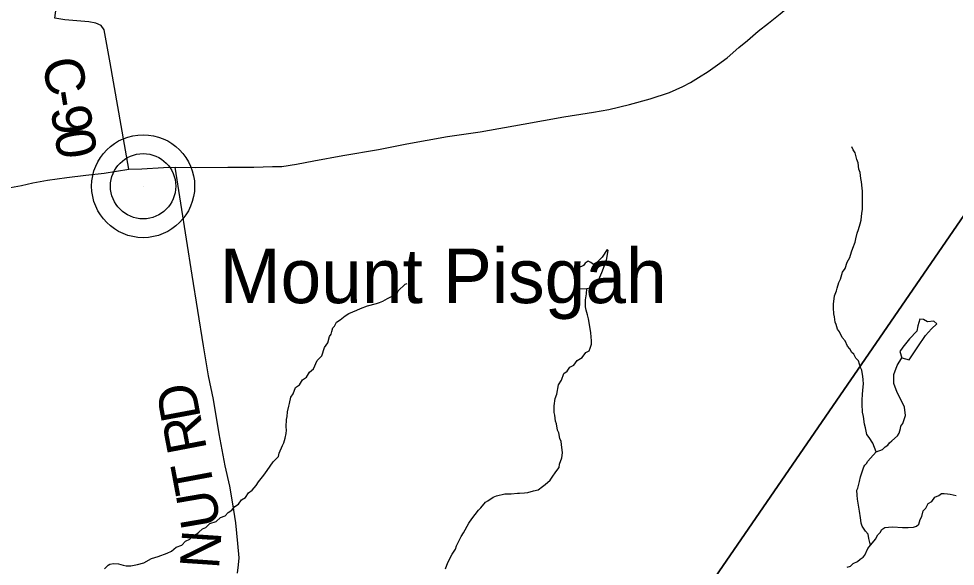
# Model space of a CAD drawing. Extents: x 0 to 39.3, y -3.9 to 22.
# Drawn here: x 3.453 to 4.806, y 14.774 to 15.566 of the extents above; entities that cross this region are included whole.
import ezdxf

# ---------------------------------------------------------------- set-up
doc = ezdxf.new("R2010")
doc.units = 0
for name, color, linetype in [('GM_X_Corporation', 7, 'Continuous'), ('GM_X_County_Road', 7, 'Continuous'), ('GM_X_County_Road_Text', 7, 'Continuous'), ('GM_X_Minor_Lake', 7, 'Continuous'), ('GM_X_Minor_River', 7, 'Continuous'), ('GM_X_State_Route', 7, 'Continuous'), ('GM_X_Township_Road', 7, 'Continuous'), ('GM_X_Township_Road_Text', 7, 'Continuous'), ('GM_X_Unincorporated', 7, 'Continuous'), ('GM_X_Unincorporated_Location', 7, 'Continuous'), ('GM_X_Unincorporated_Text', 7, 'Continuous')]:
    doc.layers.add(name, color=color, linetype=linetype)

msp = doc.modelspace()

# ---------------------------------------------------------------- linework, layer by layer
at = {"layer": 'GM_X_Corporation'}
for points in [[(6.2667, 17.3782), (6.0256, 17.0319), (5.8398, 16.7652), (5.744, 16.6289), (5.7424, 16.6266), (5.2028, 15.8376), (5.0728, 15.652), (4.2376, 14.4362), (4.2334, 14.4302), (3.9536, 14.0228), (3.9474, 14.0138), (3.8692, 13.9), (7.894, 13.9)], [(1.9, 13.9), (3.8692, 13.9), (3.9474, 14.0138), (3.9536, 14.0228), (4.2334, 14.4302), (4.2376, 14.4362), (5.0728, 15.652)]]:
    msp.add_lwpolyline(points, dxfattribs=at)
at = {"layer": 'GM_X_County_Road'}
msp.add_lwpolyline([(3.6118, 15.3483), (3.5847, 15.5024), (3.5762, 15.5497), (3.5717, 15.5564), (3.5644, 15.5596), (3.5541, 15.5613), (3.5196, 15.5645), (3.5047, 15.5667), (3.517, 15.6576), (3.5226, 15.7048), (3.5336, 15.7776), (3.5401, 15.8304), (3.5407, 15.8407), (3.5424, 15.8487), (3.5435, 15.8578), (3.543, 15.8618)], dxfattribs=at)
at = {"layer": 'GM_X_Minor_Lake'}
for points in [[(4.2735, 15.176), (4.2866, 15.1786), (4.2953, 15.199), (4.302, 15.2171), (4.3045, 15.2307), (4.303, 15.2323), (4.2956, 15.2214), (4.2883, 15.2135), (4.2833, 15.2106), (4.2796, 15.2137), (4.2754, 15.2156), (4.2712, 15.2123), (4.2689, 15.2093), (4.2616, 15.2056), (4.2569, 15.2)], [(4.2569, 15.2), (4.2561, 15.1928), (4.2581, 15.1814), (4.2614, 15.1752), (4.2735, 15.176)], [(4.7289, 15.0758), (4.7395, 15.0729), (4.752, 15.0917), (4.7629, 15.1079), (4.7714, 15.1176), (4.7795, 15.1247), (4.775, 15.1289), (4.7659, 15.1276), (4.7602, 15.1311), (4.7549, 15.1316), (4.7521, 15.1217), (4.7505, 15.1142)], [(4.7505, 15.1142), (4.7397, 15.1033), (4.7303, 15.0913), (4.726, 15.0846), (4.7289, 15.0758)]]:
    msp.add_lwpolyline(points, dxfattribs=at)
at = {"layer": 'GM_X_Minor_River'}
for points in [[(4.6918, 14.9395), (4.687, 14.9524), (4.6815, 14.9604), (4.6781, 14.9647), (4.6764, 14.9746), (4.6746, 14.9796), (4.6736, 14.991), (4.6718, 14.9972), (4.6713, 15.0086), (4.6714, 15.0139), (4.672, 15.0238), (4.6724, 15.028), (4.6729, 15.0341), (4.6733, 15.0375), (4.6731, 15.0443), (4.6724, 15.0485), (4.671, 15.0577), (4.6688, 15.0619), (4.6663, 15.0711), (4.6622, 15.075), (4.6593, 15.0811), (4.6563, 15.0834), (4.6537, 15.0888), (4.6504, 15.0923), (4.6471, 15.1003), (4.6426, 15.105), (4.6389, 15.113), (4.6356, 15.1169), (4.6338, 15.1238), (4.6323, 15.1272), (4.6313, 15.1349), (4.6303, 15.1395), (4.63, 15.1478), (4.6301, 15.1535), (4.631, 15.1611), (4.6315, 15.1653), (4.6343, 15.1725), (4.6355, 15.1763), (4.6379, 15.1846), (4.6403, 15.1892), (4.6428, 15.1994), (4.6471, 15.2046), (4.6499, 15.2141), (4.6534, 15.2205), (4.6562, 15.2289), (4.6579, 15.2342), (4.6611, 15.2429), (4.6623, 15.2478), (4.6644, 15.2561), (4.666, 15.261), (4.6684, 15.2694), (4.67, 15.2747), (4.671, 15.2846), (4.6718, 15.2902), (4.6721, 15.307), (4.6719, 15.3165), (4.6716, 15.3211), (4.6706, 15.3302), (4.6696, 15.3348), (4.6686, 15.3436), (4.6668, 15.3486), (4.6658, 15.3577), (4.6636, 15.3623), (4.6615, 15.3719), (4.6582, 15.3765), (4.6563, 15.3807)], [(3.8283, 14.9332), (3.8291, 14.9378), (3.8339, 14.9491), (3.8359, 14.9525), (3.8379, 14.9597), (3.8392, 14.9661), (3.8396, 14.9711), (3.8393, 14.976), (3.8399, 14.9863), (3.8404, 14.9909), (3.8413, 14.9977), (3.8429, 15.0057), (3.8441, 15.0098), (3.8458, 15.0189), (3.8493, 15.0238), (3.8529, 15.0325), (3.8583, 15.0366), (3.8626, 15.0438), (3.8684, 15.0475), (3.8727, 15.055), (3.8785, 15.0599), (3.8841, 15.0719), (3.8907, 15.0783), (3.8947, 15.0908), (3.8994, 15.0972), (3.9019, 15.1067), (3.9042, 15.1097), (3.905, 15.1138), (3.9066, 15.1188), (3.909, 15.1214), (3.9117, 15.127), (3.9171, 15.1308), (3.9245, 15.1363), (3.9299, 15.1397), (3.9414, 15.1444), (3.9467, 15.147), (3.9567, 15.1506), (3.9697, 15.1542), (3.9739, 15.1557), (3.9789, 15.1575), (3.9824, 15.1597), (3.9854, 15.1612), (3.9924, 15.1649), (3.9997, 15.1689), (4.0012, 15.1723), (4.0109, 15.1821), (4.014, 15.1831)], [(4.2804, 15.0956), (4.2805, 15.1002), (4.2796, 15.112), (4.2778, 15.1211), (4.2761, 15.1322), (4.2747, 15.1379), (4.2725, 15.1445), (4.2719, 15.1494), (4.2719, 15.1525), (4.2716, 15.1567), (4.2717, 15.1597), (4.273, 15.168), (4.2735, 15.176)], [(4.0694, 14.7707), (4.0726, 14.7798), (4.0789, 14.7915), (4.084, 14.799), (4.0852, 14.8039), (4.0919, 14.8175), (4.0954, 14.8228), (4.1033, 14.8367), (4.1076, 14.8428), (4.117, 14.8555), (4.1204, 14.8589), (4.1274, 14.8668), (4.1305, 14.869), (4.1382, 14.8742), (4.1432, 14.876), (4.1551, 14.8789), (4.1642, 14.8791), (4.1734, 14.8801), (4.1764, 14.88), (4.1836, 14.8803), (4.1882, 14.881), (4.1966, 14.8831), (4.2031, 14.8849), (4.2097, 14.8894), (4.2135, 14.8927), (4.2205, 14.8987), (4.2236, 14.9032), (4.2287, 14.9107), (4.2334, 14.9171), (4.2342, 14.9217), (4.2375, 14.9311), (4.2384, 14.9383), (4.2381, 14.9425), (4.2374, 14.946), (4.2364, 14.9548), (4.2345, 14.959), (4.2332, 14.967), (4.2313, 14.9712), (4.23, 14.98), (4.2285, 14.9842), (4.2275, 14.9926), (4.2265, 14.9964), (4.2262, 15.0033), (4.2266, 15.0063), (4.228, 15.0166), (4.2304, 15.023), (4.2329, 15.0366), (4.2368, 15.0434), (4.2404, 15.0529), (4.2451, 15.0562), (4.249, 15.0623), (4.2547, 15.0648), (4.2598, 15.072), (4.2671, 15.076), (4.2722, 15.0832), (4.2768, 15.0858), (4.2784, 15.0895), (4.2804, 15.0956)], [(4.7274, 14.977), (4.7303, 14.9807), (4.734, 14.9924), (4.7326, 15.0042), (4.7271, 15.0153), (4.722, 15.0257), (4.7173, 15.0383), (4.7171, 15.0513), (4.7219, 15.0645), (4.7289, 15.0758)], [(4.6833, 14.8049), (4.6812, 14.8145), (4.6801, 14.8206), (4.6764, 14.8248), (4.6716, 14.8322), (4.6701, 14.8364), (4.6695, 14.841), (4.6691, 14.8444), (4.6678, 14.8539), (4.6664, 14.8597), (4.6647, 14.8711), (4.664, 14.8772), (4.6638, 14.8844), (4.665, 14.8871), (4.6674, 14.8969), (4.6691, 14.9034), (4.6739, 14.9178), (4.6755, 14.9204), (4.6778, 14.923), (4.6794, 14.9264), (4.6833, 14.9305), (4.6918, 14.9395), (4.701, 14.9432), (4.7049, 14.9469), (4.7083, 14.9495), (4.7107, 14.9525), (4.7145, 14.9555), (4.7223, 14.963), (4.725, 14.9668), (4.7267, 14.9736), (4.7274, 14.977)], [(3.5768, 14.7704), (3.5818, 14.776), (3.5845, 14.7771), (3.5899, 14.7782), (3.5967, 14.7777), (3.6035, 14.7757), (3.6081, 14.7748), (3.6145, 14.7747), (3.6172, 14.7754), (3.6245, 14.7768), (3.6333, 14.779), (3.6448, 14.7856), (3.6544, 14.7885), (3.6674, 14.7932), (3.6735, 14.7962), (3.6801, 14.8018), (3.6882, 14.8047), (3.6936, 14.8103), (3.7001, 14.8132), (3.7048, 14.8188), (3.7102, 14.821), (3.7129, 14.8236), (3.7183, 14.8285), (3.7233, 14.8303), (3.7287, 14.8359), (3.7379, 14.8392), (3.7445, 14.8448), (3.751, 14.847), (3.7553, 14.8522), (3.7606, 14.8552), (3.7649, 14.8608), (3.7703, 14.8638), (3.7746, 14.8702), (3.7804, 14.8739), (3.7847, 14.8803), (3.7901, 14.8844), (3.7956, 14.8911), (3.7991, 14.8964), (3.8069, 14.9062), (3.8116, 14.9129), (3.8205, 14.9253), (3.8283, 14.9332)], [(4.7378, 14.8303), (4.7454, 14.8309), (4.75, 14.8323), (4.7535, 14.8353), (4.7551, 14.8421), (4.7575, 14.8463), (4.7595, 14.8546), (4.7634, 14.8584), (4.7666, 14.8648), (4.772, 14.8681), (4.7766, 14.8741), (4.7824, 14.8767), (4.7862, 14.8793), (4.7901, 14.8796), (4.7946, 14.8792), (4.7984, 14.8783), (4.8071, 14.8767)], [(4.6499, 14.7728), (4.6545, 14.7742), (4.6584, 14.778), (4.6646, 14.7809), (4.6684, 14.7843), (4.6731, 14.7876), (4.6754, 14.7902), (4.6797, 14.7997), (4.6833, 14.8049), (4.6887, 14.8109), (4.6907, 14.8136), (4.6942, 14.8196), (4.6973, 14.823), (4.6997, 14.8275), (4.7043, 14.8305), (4.7096, 14.8307), (4.7157, 14.8314), (4.7298, 14.8304), (4.7378, 14.8303)]]:
    msp.add_lwpolyline(points, dxfattribs=at)
at = {"layer": 'GM_X_State_Route'}
for points in [[(4.2743, 15.4296), (4.2833, 15.4311), (4.3054, 15.4346), (4.3352, 15.4421), (4.3653, 15.4504), (4.3932, 15.4595), (4.4122, 15.4682), (4.4234, 15.4738), (4.435, 15.481), (4.4487, 15.4895), (4.4623, 15.4992), (4.4766, 15.5093), (4.4931, 15.5243), (4.5057, 15.5343), (4.5214, 15.548), (4.5359, 15.5594), (4.553, 15.5731), (4.5764, 15.5926), (4.6098, 15.6159), (4.6349, 15.6332), (4.6665, 15.6543), (4.6902, 15.6706), (4.7092, 15.6837)], [(3.4411, 15.3218), (3.4568, 15.325), (3.4729, 15.3288), (3.4942, 15.3324), (3.5224, 15.3366), (3.5498, 15.34), (3.5764, 15.3427), (3.6118, 15.3483), (3.6305, 15.349), (3.662, 15.351), (3.6787, 15.3512), (3.7076, 15.351), (3.7551, 15.3512), (3.7926, 15.3514), (3.8193, 15.3521), (3.8329, 15.3523), (3.8541, 15.3557), (3.879, 15.3606), (3.9209, 15.3682), (3.9726, 15.3768), (4.0133, 15.3852), (4.0723, 15.3955), (4.1193, 15.4023), (4.1818, 15.4137), (4.2405, 15.424), (4.2743, 15.4296)]]:
    msp.add_lwpolyline(points, dxfattribs=at)
at = {"layer": 'GM_X_Township_Road'}
msp.add_line((3.7034, 15.1952), (3.6787, 15.3512), dxfattribs=at)
msp.add_lwpolyline([(3.769, 14.7645), (3.7704, 14.7763), (3.7712, 14.7863), (3.7694, 14.8073), (3.7666, 14.8371), (3.7622, 14.8643), (3.7578, 14.8901), (3.751, 14.9197), (3.7425, 14.9657), (3.7341, 15.0154), (3.7271, 15.0494), (3.7197, 15.0928), (3.7034, 15.1952)], dxfattribs=at)
at = {"layer": 'GM_X_Unincorporated'}
for radius in [0.0744, 0.0472]:
    msp.add_circle((3.6325, 15.3238), radius, dxfattribs=at)
at = {"layer": 'GM_X_Unincorporated_Location'}
msp.add_line((3.6325, 15.3238), (3.6325, 15.3238), dxfattribs=at)

# ---------------------------------------------------------------- texts
at = {"layer": 'GM_X_County_Road_Text'}
for s, rotation, p in [('C', 280.5984, (3.4863, 15.505)), ('-', 279.1563, (3.4948, 15.4595)), ('9', 278.9717, (3.4985, 15.4365)), ('0', 278.9191, (3.504, 15.402))]:
    msp.add_text(s, height=0.0568, rotation=rotation, dxfattribs=at).set_placement(p)
at = {"layer": 'GM_X_Township_Road_Text'}
for s, rotation, p in [('D', 100.6137, (3.7161, 14.9892)), ('R', 100.886, (3.7249, 14.9434)), ('T', 100.5953, (3.7361, 14.8842)), ('U', 99.7382, (3.7447, 14.834)), ('N', 86.1332, (3.7421, 14.7694))]:
    msp.add_text(s, height=0.0568, rotation=rotation, dxfattribs=at).set_placement(p)
at = {"layer": 'GM_X_Unincorporated_Text'}
msp.add_text('Mount Pisgah', height=0.078977, rotation=0, dxfattribs=at).set_placement((3.7431, 15.1547))

doc.saveas('drawing.dxf')
